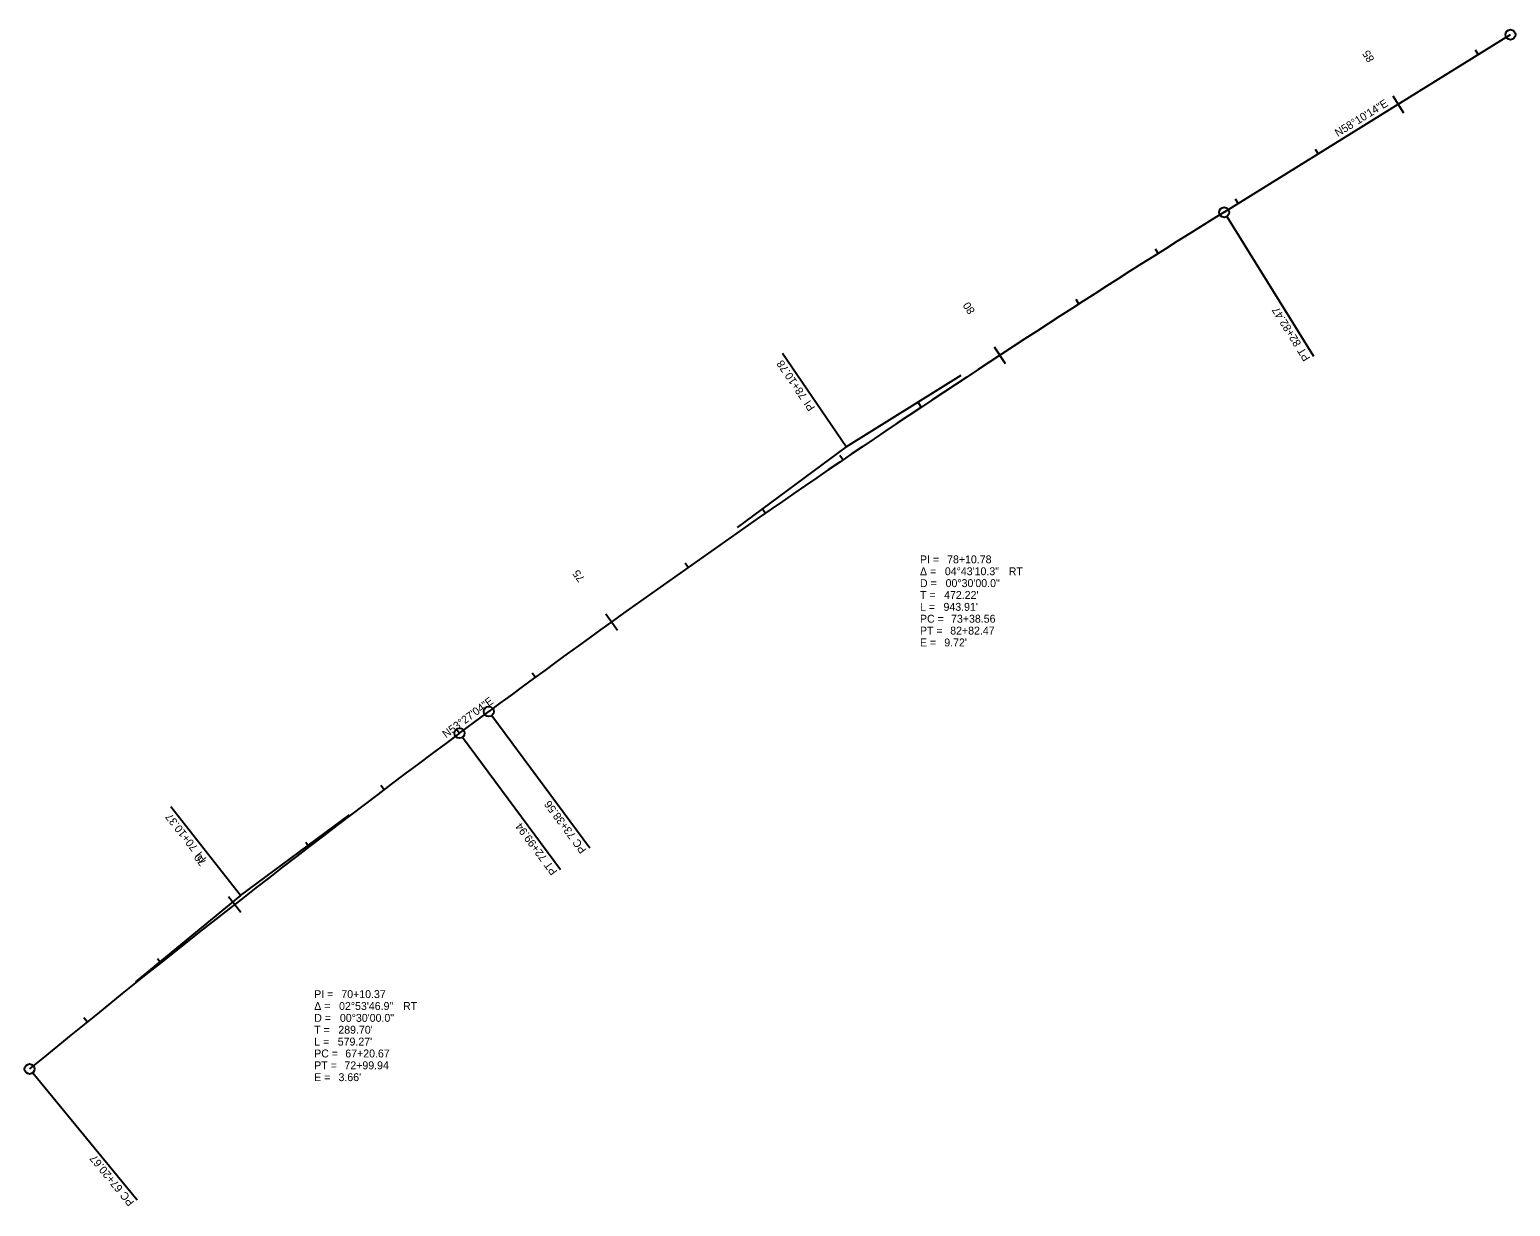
# Model space of a CAD drawing. Extents: x 1145421 to 1155673, y 2015317 to 2021442.
# Drawn here: x 1149640 to 1151212, y 2018962 to 2020212 of the extents above; entities that cross this region are included whole.
import ezdxf

# ---------------------------------------------------------------- set-up
doc = ezdxf.new("R2010")
doc.units = 0
for name, color, linetype in [('Default', 7, 'Continuous'), ('EX_CONTOUR_ANNOT_MINOR', 7, 'Continuous'), ('EX_TERRAIN', 7, 'Continuous')]:
    doc.layers.add(name, color=color, linetype=linetype)

msp = doc.modelspace()

# ---------------------------------------------------------------- linework, layer by layer
at = {"layer": 'Default'}
for p, q in [((1150907.9, 2020018.1), (1151211.9, 2020206.8)), ((1150096.3, 2019464.9), (1150127.3, 2019487.9))]:
    msp.add_line(p, q, dxfattribs=at)
for centre, start, end in [((1156951.4, 2010282.2), 121.82944, 126.54898), ((1156920.4, 2010259.2), 126.54898, 129.44534)]:
    msp.add_arc(centre, 11459.2, start, end, dxfattribs=at)
at = {"layer": 'EX_CONTOUR_ANNOT_MINOR'}
for p, q in [((1151211.9, 2020206.8), (1151211.9, 2020206.8)), ((1151174.5, 2020190.7), (1151177.7, 2020185.6)), ((1151087.1, 2020141.9), (1151098.3, 2020123.9)), ((1151004.6, 2020085.2), (1151007.8, 2020080.1)), ((1150919.6, 2020032.5), (1150922.8, 2020027.4)), ((1150907.9, 2020018.1), (1150907.9, 2020018.1)), ((1150910.7, 2020013.6), (1151002.8, 2019865.2)), ((1150834.8, 2019979.5), (1150838, 2019974.4)), ((1150750.4, 2019925.7), (1150753.7, 2019920.7)), ((1150506.7, 2019769.1), (1150439.3, 2019868.3)), ((1150439.3, 2019868.3), (1150439.3, 2019868.3)), ((1150663.9, 2019875.1), (1150675.6, 2019857.4)), ((1151002.8, 2019865.2), (1151002.8, 2019865.2)), ((1150506.7, 2019769.1), (1150629, 2019845)), ((1150583.1, 2019816), (1150586.4, 2019811)), ((1150506.7, 2019769.1), (1150391, 2019683.3)), ((1150500.1, 2019760.1), (1150503.5, 2019755.1)), ((1150417.6, 2019703.4), (1150421.1, 2019698.5)), ((1150335.7, 2019646), (1150339.1, 2019641.1)), ((1150251.5, 2019591.8), (1150263.9, 2019574.5)), ((1150173.3, 2019529.2), (1150176.8, 2019524.3)), ((1150127.3, 2019487.9), (1150127.3, 2019487.9)), ((1150130.5, 2019483.6), (1150234.5, 2019343.3)), ((1150092.8, 2019469.7), (1150096.4, 2019464.9)), ((1150096.3, 2019464.9), (1150096.3, 2019464.9)), ((1150099.5, 2019460.6), (1150203.5, 2019320.3)), ((1150012.7, 2019409.8), (1150016.3, 2019405)), ((1149863.6, 2019292.4), (1149789.7, 2019386.9)), ((1149789.7, 2019386.9), (1149789.7, 2019386.9)), ((1149863.6, 2019292.4), (1149979.3, 2019378.1)), ((1149933.1, 2019349.2), (1149936.7, 2019344.4)), ((1150234.5, 2019343.3), (1150234.5, 2019343.3)), ((1150203.5, 2019320.3), (1150203.5, 2019320.3)), ((1149863.6, 2019292.4), (1149752.4, 2019200.9)), ((1149851.1, 2019291.5), (1149864.2, 2019274.8)), ((1149775.5, 2019225.8), (1149779.2, 2019221.1)), ((1149697.5, 2019163.1), (1149701.3, 2019158.5)), ((1149639.9, 2019108.3), (1149639.9, 2019108.3)), ((1149643.3, 2019104.2), (1149754.2, 2018969.3)), ((1149754.2, 2018969.3), (1149754.2, 2018969.3))]:
    msp.add_line(p, q, dxfattribs=at)
for centre in [(1151211.9, 2020206.8), (1150907.9, 2020018.1), (1150127.3, 2019487.9), (1150096.3, 2019464.9), (1149639.9, 2019108.3)]:
    msp.add_circle(centre, 5.34, dxfattribs=at)
at = {"layer": 'EX_TERRAIN'}
for p, q in [((1150907.9, 2020018.1), (1151211.9, 2020206.8)), ((1150096.3, 2019464.9), (1150127.3, 2019487.9))]:
    msp.add_line(p, q, dxfattribs=at)
for centre, start, end in [((1156951.4, 2010282.2), 121.82944, 126.54898), ((1156920.4, 2010259.2), 126.54898, 129.44534)]:
    msp.add_arc(centre, 11459.2, start, end, dxfattribs=at)

# ---------------------------------------------------------------- texts
at = {"layer": 'EX_CONTOUR_ANNOT_MINOR'}
for s, rotation, p in [('85', 121.8294, (1151067.9, 2020180.7)), ('N58°10\'14"E', 31.8294, (1151028.7, 2020098)), ('80', 123.2418, (1150643.9, 2019913.4)), ('82+82.47', 121.8294, (1150990.2, 2019878.7)), ('PT', 121.8294, (1150999.8, 2019863.3)), ('78+10.78', 124.1892, (1150465.7, 2019823)), ('PI ', 124.1892, (1150474.1, 2019810.7)), ('75', 125.7418, (1150229.7, 2019629.2)), ('N53°27\'04"E', 36.549, (1150081.9, 2019459.4)), ('73+38.56', 126.549, (1150220.3, 2019356.4)), ('70+10.37', 127.9972, (1149819, 2019343.6)), ('72+99.94', 126.549, (1150189.8, 2019332.7)), ('PC', 126.549, (1150231.6, 2019341.1)), ('70', 128.0487, (1149828, 2019328)), ('PI ', 127.9972, (1149828.2, 2019331.9)), ('PT', 126.549, (1150200.6, 2019318.1)), ('67+20.67', 129.4453, (1149739.4, 2018981.7)), ('PC', 129.4453, (1149751.5, 2018967))]:
    msp.add_text(s, height=8.4, rotation=rotation, dxfattribs=at).set_placement(p)
for s, p in [('PI = ', (1150585.1, 2019645.3)), ('78+10.78', (1150613.9, 2019645.3)), ('Δ = ', (1150585.1, 2019632.7)), ('04°43\'10.3"', (1150611.5, 2019632.7)), (' RT', (1150676.2, 2019632.7)), ('T = ', (1150585.1, 2019607.5)), ('D = ', (1150585.1, 2019620.1)), ("472.22'", (1150610.7, 2019607.5)), ('00°30\'00.0"', (1150612.3, 2019620.1)), ('L = ', (1150585.1, 2019594.9)), ("943.91'", (1150610.1, 2019594.9)), ('PC = ', (1150585.1, 2019582.3)), ('73+38.56', (1150618.1, 2019582.3)), ('PT = ', (1150585.1, 2019569.7)), ('82+82.47', (1150617.2, 2019569.7)), ('E = ', (1150585.1, 2019557.1)), ("9.72'", (1150610.9, 2019557.1)), ('PI = ', (1149942, 2019183.6)), ('70+10.37', (1149970.8, 2019183.6)), ('Δ = ', (1149942, 2019171)), ('02°53\'46.9"', (1149968.4, 2019171)), (' RT', (1150033.2, 2019171)), ('D = ', (1149942, 2019158.4)), ('00°30\'00.0"', (1149969.3, 2019158.4)), ('T = ', (1149942, 2019145.8)), ("289.70'", (1149967.6, 2019145.8)), ('L = ', (1149942, 2019133.2)), ('PC = ', (1149942, 2019120.6)), ("579.27'", (1149967, 2019133.2)), ('67+20.67', (1149975, 2019120.6)), ('PT = ', (1149942, 2019108)), ('72+99.94', (1149974.1, 2019108)), ('E = ', (1149942, 2019095.4)), ("3.66'", (1149967.8, 2019095.4))]:
    msp.add_text(s, height=8.4, dxfattribs=at).set_placement(p)

doc.saveas('drawing.dxf')
